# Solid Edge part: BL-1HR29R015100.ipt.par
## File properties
Author: mate.vegh
Template: iso metric part.par
Last saved by: mate.vegh
Revision: 7
Application: Solid Edge
Company: Bearing Kft
Sűrűség: 0,000 kg/m^3
Pontosság: 0,990
Username: mate.vegh
Dokumentum tartalom típus: 0
Document Number: BEX-
Project Name: BEX-
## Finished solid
Body 1: solid body, 1535 faces, 4434 edges, 2948 vertices.
  Faces by surface: plane 1056, swept 477, cylinder 2
  Edges by curve: line 3476, circle 404, intersection 400, spline 154
Bounding box of the edges (mm; curved faces can reach further): 1007.272 x 20.000 x 20.500, from (-7.2708, -20, -20.5) to (1000.0016, 0, 0).
Cylindrical faces by radius (mm): R0.8965 x1, R0.9502 x1
Planar faces by outward normal: +x 37, +y 40, +z 1, -x 40, -y 450, -z 54, oblique 434
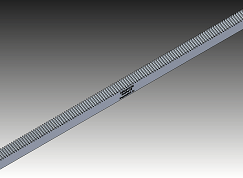
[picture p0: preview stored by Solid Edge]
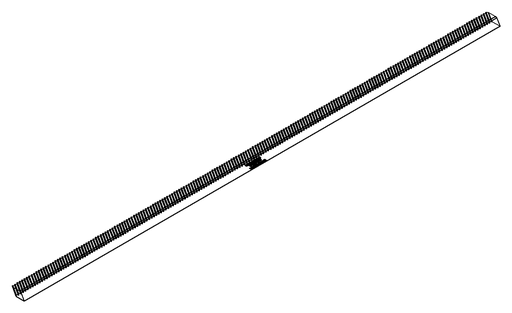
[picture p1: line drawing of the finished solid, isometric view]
